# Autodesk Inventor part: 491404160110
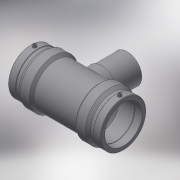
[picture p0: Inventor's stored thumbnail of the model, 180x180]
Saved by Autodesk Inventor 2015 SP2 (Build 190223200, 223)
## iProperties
Created: 2017-06
Part Number: 491404160110
Material: Generic
Description: PLASSON REDUCING TEE 160x110x160
Document SubType Name: Modeling
Designer: KIM
Mass: 5434.22 g
Surface Area: 5676.22 cm^2
Volume: 5434.22 cm^3
Density: 1 g/cm^3
Appearance: Default
Author: KIM
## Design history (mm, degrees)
derived "491404.ipt"
feature "Solid1::491404.ipt"
tag "TaggingFeature1"
body "Solid1"
other parameters: "d2" = 208, "d3" = 86, "d4" = 88, "d5" = 187.2, "d6" = 152, "d8" = 168 deg, "d10" = 34.4, "d11" = 11.46667, "d14" = 17.6296, "d17" = 144, "d19" = 3.52592, "d20" = 168 deg, "d22" = 193.44, "d23" = 208, "d25" = 135 deg, "d26" = 308, "d29" = 106, "d30" = 15, "d31" = 176, "d34" = 5 deg, "d35" = 15, "d39" = 5 deg, "d41" = 4, "d42" = 14, "d43" = 0, "d45" = 4, "d46" = 6, "d47" = 0, "d48" = -193, "d51" = 0, "d52" = 88, "d54" = 0, "d55" = 187.2, "d56" = 208, "d57" = 154, "d58" = 135 deg, "d59" = 86, "d60" = 86, "d61" = 135 deg, "d62" = 193, "d72" = 200.2, "d73" = 100.1, "d74" = -193, "d75" = 115.5, "d77" = 0, "d78" = 88, "d80" = 0, "d82" = 89, "d83" = 0, "d84" = 3, "d85" = 0, "d86" = 28.66667, "d87" = 189.5712, "d88" = 11.46667, "d89" = 3, "d90" = 0, "L_1" = 86, "D_" = 208, "A_" = 106, "d_2" = 12, "H_" = 193
